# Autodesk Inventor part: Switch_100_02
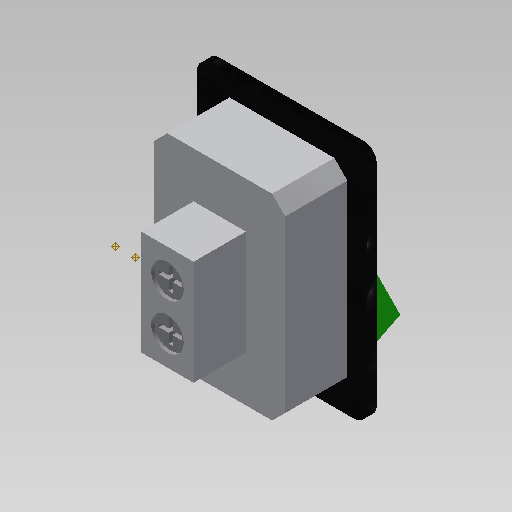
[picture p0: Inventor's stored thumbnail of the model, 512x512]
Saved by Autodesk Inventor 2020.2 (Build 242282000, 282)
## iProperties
Created: 2014-09
Part Number: Switch_100_02
Material: Ogólny
Document SubType Name: Modeling
Designer: F.Stasiak
Density: 1 g/cm^3
Appearance: Domyślna
Categories: <MemberInstance><Categories><Category DisplayName="" Mnemonic="CABLEANDHARNESS" InternalName="e4a7e005-5e42-4d16-b293-125e7f0d0512"><Category DisplayName="" Mne
Catalog Web Link: www.expertbooks.pl
Manager: www.cadconsulting.pl
Company: Fabian Stasiak CAD Consulting
GlobalPropertyList: <PropertyList/>
Author: F.Stasiak
Subject: Zbiór ćwiczeń. Autodesk Inventor 2020. Kurs Professional
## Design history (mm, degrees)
sketch "Szkic1"
  geometry: L1 (-10, 15)-(10, 15); L2 (10, 15)-(10, -15); L3 (10, -15)-(-10, -15); L4 (-10, -15)-(-10, 15); L5 (-10, 15)-(10, -15); L6 (10, 15)-(-10, -15); 1 further point
  constraints: 12 end point, 2 equal length, 2 midpoint, 1 horizontal, 1 parallel
  dimensions: "d0" = 20 distance of L2.end L3.end; "d1" = 30 distance of L1.end L2.end
extrude "Wyciągnięcie proste1" new body sketch "Szkic1" distance "d2" = 12; taper "d3" = 0 deg
node "Płaszczyzna konstrukcyjna1"
sketch "Szkic2"
  geometry: L1 (10, 15)-(-10, 15) reference; L2 (-10, 15)-(-10, -15) reference; L3 (-10, -15)-(10, -15) reference; L4 (10, -15)-(10, 15) reference; L5 (-13, 18)-(13, 18); L6 (13, 18)-(13, -18); L7 (13, -18)-(-13, -18); L8 (-13, -18)-(-13, 18); 1 further point
  constraints: 8 end point, 3 other
  dimensions: "d5" = 3 distance between parallel lines of L1 L5
extrude "Wyciągnięcie proste2" join sketch "Szkic2" distance "d6" = 1.5; taper "d7" = 0 deg
fillet "Zaokrąglenie1" dims "d8" = 2
chamfer "Faza1" distance "d9" = 2; stored, may be unused: second distance "d10" = 2, angle "d11" = 45 deg
sketch "Szkic3"
  geometry: L1 (15, 0)-(-15, 0) reference; L2 (-15, 0)-(15, 0) reference; L3 (13.059, 0)-(13.059, -1.168); L4 (13.059, -1.168)-(0.743, -1.599); L5 (0.743, -1.599)-(-10.298, -7.075); L6 (-10.298, -7.075)-(-13.229, -1.168); L7 (-13.229, -1.168)-(-13.229, 0); 1 further point
  constraints: 10 end point, 3 perpendicular, 2 equal length, 2 point on line
extrude "Wyciągnięcie proste3" join sketch "Szkic3" stored distance "d12" = 17; taper "d13" = 0 deg
sketch "Szkic4"
  geometry: L1 (4, 8)-(-4, 8); L2 (-4, 8)-(-4, -8); L3 (-4, -8)-(4, -8); L4 (4, -8)-(4, 8); L5 (4, 8)-(-4, -8); L6 (-4, 8)-(4, -8); 1 further point
  constraints: 12 end point, 2 midpoint, 2 parallel, 1 horizontal, 1 perpendicular
  dimensions: "d14" = 8 distance of L3.end L2.end; "d15" = 16 distance of L2.end L1.end
extrude "Wyciągnięcie proste4" join sketch "Szkic4" distance "d16" = 8; taper "d17" = 0 deg
sketch "Szkic5"
  geometry: L1 (0, 0)-(0, 16) reference; L2 (0, 0)-(8, 0) reference; L3 (8, 16)-(8, 0) reference; L4 (0, 16)-(8, 16) reference; L5 (4, 11.5)-(4, 4.5); C1 r 2 at (4, 11.5); C2 r 2 at (4, 4.5); 5 further points
  constraints: 4 midpoint, 2 centre point, 2 end point, 2 vertical alignment, 1 equal radius, 1 horizontal alignment, 1 vertical
  dimensions: "d18" = 4 diameter of C1; "d19" = 7 distance of L5.end L5.start
extrude "Wyciągnięcie proste5" cut sketch "Szkic5" distance "d20" = 5; taper "d21" = 0 deg
sketch "Szkic6"
  geometry: L1 (1, 1.5)-(1, 5.5) reference; L2 (-4, 1.5)-(-4, 5.5) reference; L3 (1, -5.5)-(1, -1.5) reference; L4 (-4, -5.5)-(-4, -1.5) reference; L5 (4, 8)-(-4, 8) reference; L6 (-4, 8)-(-4, -8) reference; L7 (-4, -8)-(4, -8) reference; L8 (4, -8)-(4, 8) reference; C1 r 2.5 at (0, 3.5); C2 r 2.5 at (0, -3.5); 2 further points
  constraints: 2 centre point, 2 midpoint, 2 vertical alignment, 1 equal radius
  dimensions: "d22" = 7 distance of C1.centre C2.centre; "d23" = 5 diameter of C2
extrude "Wyciągnięcie proste6" cut sketch "Szkic6" distance "d24" = 0.5; taper "d25" = 0 deg
sketch "Szkic7"
  geometry: L1 (0.3, 1.75)-(-0.3, 1.75); L2 (-0.3, 1.75)-(-0.3, -1.75); L3 (-0.3, -1.75)-(0.3, -1.75); L4 (0.3, -1.75)-(0.3, 1.75); L5 (0.3, 1.75)-(-0.3, -1.75); L6 (-0.3, 1.75)-(0.3, -1.75); L7 (1.8, 0.3)-(-1.8, 0.3); L8 (-1.8, 0.3)-(-1.8, -0.3); L9 (-1.8, -0.3)-(1.8, -0.3); L10 (1.8, -0.3)-(1.8, 0.3); L11 (1.8, 0.3)-(-1.8, -0.3); L12 (-1.8, 0.3)-(1.8, -0.3); 3 further points
  constraints: 24 end point, 5 midpoint, 4 parallel, 2 horizontal, 2 perpendicular
  dimensions: "d26" = 0.6 distance of L3.end L2.end; "d27" = 3.5 distance of L2.end L1.end; "d28" = 3.6 distance of L9.end L8.end; "d29" = 0.6 distance of L8.end L7.end
extrude "Wyciągnięcie proste7" cut sketch "Szkic7" distance "d30" = 1; taper "d31" = -5 deg
mirror "Odbicie lustrzane1"
chamfer "Faza2" distance "d32" = 1; stored, may be unused: second distance "d33" = 2, angle "d34" = 45 deg
chamfer "Faza3" distance "d35" = 1; stored, may be unused: second distance "d36" = 2, angle "d37" = 45 deg
sketch "Szkic8"
  geometry: C1 r 2 at (4, 11.5) reference
node "S1"
sketch "Szkic9"
  geometry: C1 r 2 at (4, 4.5) reference
node "S2"
node "Płaszczyzna konstrukcyjna2"
node "Płaszczyzna konstrukcyjna3"
node "Punkt konstrukcyjny3"
node "Płaszczyzna konstrukcyjna4"
node "Punkt konstrukcyjny4"
node "Bryła1"
node "Pętla rzutowana1"
node "Pętla rzutowana2"
node "Pętla rzutowana3"
node "Pętla rzutowana4"
node "Pętla rzutowana5"
other parameters: "d4" = -1, "d38" = 5, "d39" = 3
